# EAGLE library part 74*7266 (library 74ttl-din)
Quad 2-input XNOR
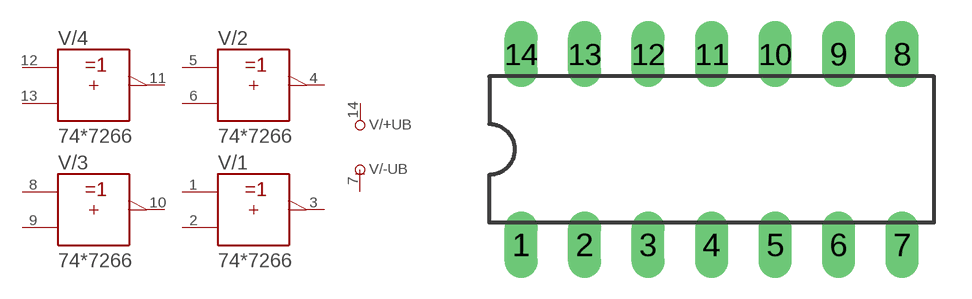
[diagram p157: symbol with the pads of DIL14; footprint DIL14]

Designator prefix V; gates /+UB=+UB /-UB=-UB /1=7266 /2=7266 /3=7266 /4=7266

## 747266N  [DIL14]
1  /1:A  in
2  /1:B  in
3  /1:Y  out
4  /2:Y  out
5  /2:A  in
6  /2:B  in
7  /-UB:-UB  pwr
8  /3:A  in
9  /3:B  in
10  /3:Y  out
11  /4:Y  out
12  /4:A  in
13  /4:B  in
14  /+UB:+UB  pwr

## Footprint DIL14 (pad centres in mm)
Dual In Line Package
drill 0.813 long: 1 -7.62,-3.81; 2 -5.08,-3.81; 3 -2.54,-3.81; 4 0,-3.81; 5 2.54,-3.81; 6 5.08,-3.81; 7 7.62,-3.81; 8 7.62,3.81; 9 5.08,3.81; 10 2.54,3.81; 11 0,3.81; 12 -2.54,3.81; 13 -5.08,3.81; 14 -7.62,3.81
